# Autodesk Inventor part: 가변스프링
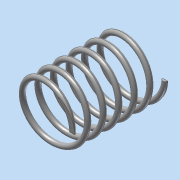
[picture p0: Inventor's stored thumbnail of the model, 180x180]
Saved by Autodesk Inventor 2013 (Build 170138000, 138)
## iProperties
Created: 2018-06
Part Number: 가변스프링
Material: 강철, 연강
Document SubType Name: Modeling
Designer: Administrator
Density: 7.86 g/cm^3
Mass: 82.807 g
Surface Area: 106.473 cm^2
Volume: 10.5352 cm^3
Author: Administrator
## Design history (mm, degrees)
sketch "스케치1"
  geometry: L1 (0, 0)-(0, 73.25); L2 (22.5, 0)-(0, 0); L3 (0, 73.25)-(22.5, 73.25); C1 r 2 at (22.5, 0)
  constraints: 6 end point, 1 centre point, 1 parallel, 1 perpendicular, 1 vertical
  dimensions: "d0" = 73.25 distance of L1.start L1.end (derived); "d1" = 4 diameter of C1; "d2" = 45 diameter of L2.start L1; "d3" = 22.5 distance of L1.end L3.end
feature "코일1" sketch "스케치1" pitch "d4" = 10; turns "d6" = 6; dims "d5" = 73.25 (= d0), "d7" = 0, angle "d8" = 90 deg, angle "d9" = 90 deg, "d10" = 0, "d11" = 0
sketch "스케치2"
  geometry: L1 (73.25, 27.5)-(0, 27.5); L2 (0, 27.5)-(0, -27.5); L3 (0, -27.5)-(73.25, -27.5); L4 (73.25, -27.5)-(73.25, 27.5); 2 further points
  constraints: 8 end point, 2 parallel, 1 coincident, 1 horizontal, 1 midpoint, 1 perpendicular
  dimensions: "d12" = 73.25 distance of L1.start L1.end (derived); "d14" = 55 distance of L3.end L1.start
extrude "돌출2" sketch "스케치2" stored distance "d17" = 10; taper "d18" = 0 deg
node "솔리드1"
